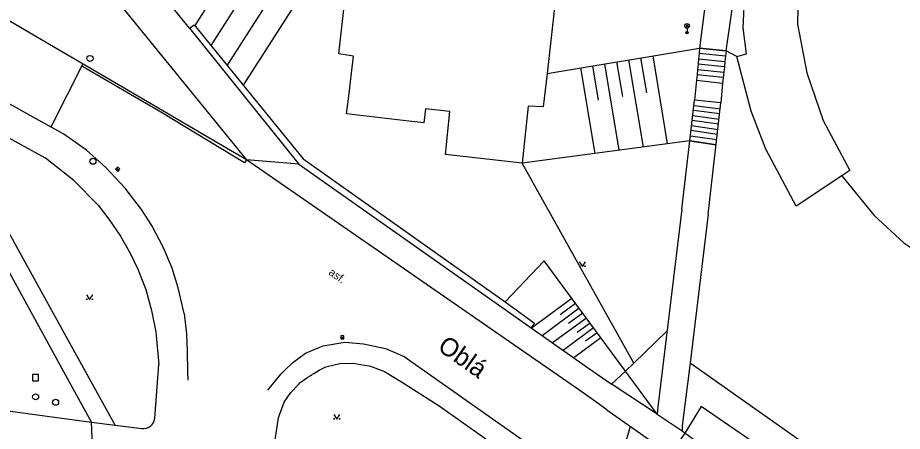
# Model space of a CAD drawing. Extents: x -602419 to -601554, y -1162937 to -1162362.
# Drawn here: x -602032.9 to -601960.3, y -1162522.5 to -1162488.6 of the extents above; entities that cross this region are included whole.
import ezdxf

# ---------------------------------------------------------------- set-up
doc = ezdxf.new("R2010")
doc.units = 0
doc.layers.add('Podklad', color=7, linetype='Continuous')

msp = doc.modelspace()

# ---------------------------------------------------------------- linework, layer by layer
at = {"layer": 'Podklad'}
for p, q in [((-601978.0925, -1162489.38), (-601977.8275, -1162489.115)), ((-601978.0925, -1162489.115), (-601977.8275, -1162489.38)), ((-601977.96, -1162489.435), (-601977.96, -1162489.81)), ((-602024.7616, -1162500.9249), (-602024.5784, -1162501.0951)), ((-602006.3692, -1162514.8113), (-602006.1192, -1162514.8113)), ((-602001.1665, -1162516.3917), (-601988.13, -1162525.56)), ((-601998.3077, -1162520.4323), (-601988.11, -1162527.62)), ((-602011.79, -1162523.58), (-602011.4808, -1162521.4155))]:
    msp.add_line(p, q, dxfattribs=at)
for points in [[(-602031.84, -1162478.48), (-602029.24, -1162481.61), (-602023.2199, -1162489.02), (-602016.15, -1162497.71), (-602014.38, -1162499.9), (-602014.09, -1162500.25)], [(-602014.09, -1162482.53), (-602018.35, -1162489.21)], [(-601974.75, -1162491.29), (-601973.52, -1162482.74)], [(-602012.4099, -1162483.61), (-602017.02, -1162490.85)], [(-601975.96, -1162483.38), (-601976.93, -1162491.06)], [(-602018.77, -1162489.42), (-602022.39, -1162484.96)], [(-602010.7199, -1162484.68), (-602015.69, -1162492.48)], [(-602009.03, -1162485.76), (-602014.36, -1162494.12)], [(-602030.92, -1162490.38), (-602037.98, -1162486.24)], [(-601965.26, -1162501.56), (-601969.02, -1162504.04), (-601971.5, -1162499.36), (-601972.71, -1162496.25), (-601973.89, -1162491.75), (-601973.08, -1162491.53), (-601973.36, -1162489.4099), (-601973.23, -1162486.48), (-601968.85, -1162486.43)], [(-601968.85, -1162486.43), (-601968.89, -1162489.1), (-601968.13, -1162493.1), (-601966.8, -1162497), (-601964.61, -1162501.12), (-601965.26, -1162501.56)], [(-602006.53, -1162491.55), (-602006.08, -1162487.64)], [(-601988.83, -1162487.74), (-601989.44, -1162493.14)], [(-602018.77, -1162489.42), (-602018.39, -1162489.1599), (-602015.19, -1162493.1), (-602013.4099, -1162495.29), (-602009.46, -1162500.15), (-601992.88, -1162511.9)], [(-602018.77, -1162489.42), (-602009.81, -1162500.58), (-601990.76, -1162514.04)], [(-602024.28, -1162494.27), (-602030.92, -1162490.38)], [(-602032.09, -1162496.4699), (-602041.27, -1162491.36)], [(-602005.31, -1162491.7199), (-602006.53, -1162491.55)], [(-601989.44, -1162493.14), (-601976.93, -1162491.06)], [(-601976.93, -1162491.06), (-601976.9699, -1162491.5), (-601977.02, -1162491.94), (-601977.06, -1162492.38), (-601977.1, -1162492.82), (-601977.14, -1162493.26), (-601977.19, -1162493.7), (-601977.34, -1162495.33)], [(-601974.8, -1162491.73), (-601976.9699, -1162491.5)], [(-601974.75, -1162491.29), (-601976.93, -1162491.06)], [(-601976.93, -1162491.06), (-601974.75, -1162491.29)], [(-601974.75, -1162491.29), (-601974.8, -1162491.73), (-601974.85, -1162492.17), (-601974.9, -1162492.61), (-601974.95, -1162493.05), (-601975, -1162493.49), (-601975.05, -1162493.94), (-601975.18, -1162495.57)], [(-601973.89, -1162491.75), (-601974.75, -1162491.29)], [(-602005.73, -1162495.2199), (-602005.31, -1162491.7199)], [(-601983.74, -1162492.19), (-601983.27, -1162495.04)], [(-601982.76, -1162492.03), (-601981.57, -1162499.19)], [(-601981.77, -1162491.86), (-601981.29, -1162494.74)], [(-601980.78, -1162491.7), (-601979.58, -1162498.92)], [(-601977.02, -1162491.94), (-601974.85, -1162492.17)], [(-602029.96, -1162497.1999), (-602027.61, -1162492.5399)], [(-602027.61, -1162492.5399), (-602027.5271, -1162492.3677)], [(-602009.81, -1162500.58), (-602014.09, -1162500.25), (-602014.2669, -1162500.497), (-602021.13, -1162496.3299), (-602027.61, -1162492.5399)], [(-601986.7, -1162492.68), (-601985.53, -1162499.7199)], [(-601985.7199, -1162492.52), (-601985.25, -1162495.35)], [(-601984.73, -1162492.36), (-601983.55, -1162499.45)], [(-601977.1, -1162492.82), (-601974.95, -1162493.05)], [(-601974.9, -1162492.61), (-601977.06, -1162492.38)], [(-601989.44, -1162493.14), (-601989.76, -1162495.9)], [(-601977.19, -1162493.7), (-601975.05, -1162493.94)], [(-601977.19, -1162493.7), (-601975.05, -1162493.94)], [(-601975, -1162493.49), (-601977.14, -1162493.26)], [(-602016.4, -1162498.89), (-602024.28, -1162494.27)], [(-602032.58, -1162499), (-602039.73, -1162495.07), (-602033.87, -1162505.71)], [(-602005.89, -1162496.4699), (-602005.73, -1162495.2199)], [(-601990.99, -1162495.83), (-601991.5, -1162500.52)], [(-601989.76, -1162495.9), (-601990.99, -1162495.83)], [(-601977.74, -1162498.67), (-601977.34, -1162495.33)], [(-601977.39, -1162495.79), (-601975.23, -1162496.05)], [(-601975.18, -1162495.57), (-601977.34, -1162495.33)], [(-601975.18, -1162495.57), (-601977.34, -1162495.33)], [(-601976.23, -1162504.71), (-601975.18, -1162495.57)], [(-602025.64, -1162500.88), (-602027.23, -1162499.44), (-602029.08, -1162498.14), (-602032.09, -1162496.4699)], [(-602000.79, -1162497.06), (-602005.89, -1162496.4699)], [(-601999.4099, -1162496.04), (-601999.56, -1162497.21)], [(-601997.42, -1162496.27), (-601999.4099, -1162496.04)], [(-601997.78, -1162499.8), (-601997.42, -1162496.27)], [(-601977.48, -1162496.61), (-601975.33, -1162496.89)], [(-601975.28, -1162496.4699), (-601977.44, -1162496.2)], [(-602030.1432, -1162497.5501), (-602030.1151, -1162497.4968), (-602030.0159, -1162497.3067), (-602029.96, -1162497.1999)], [(-601999.56, -1162497.21), (-602000.79, -1162497.06)], [(-601975.38, -1162497.32), (-601977.53, -1162497.02)], [(-601975.48, -1162498.1599), (-601977.64, -1162497.84)], [(-601977.59, -1162497.43), (-601975.42, -1162497.74)], [(-601977.74, -1162498.67), (-601991.5, -1162500.52)], [(-601978.4, -1162504.28), (-601977.74, -1162498.67)], [(-601977.74, -1162498.67), (-601975.575, -1162499.0083)], [(-601975.57, -1162499.01), (-601977.7199, -1162498.67)], [(-601977.69, -1162498.26), (-601975.53, -1162498.58)], [(-602026.27, -1162503.96), (-602028.26, -1162501.93), (-602030.58, -1162500.1), (-602032.58, -1162499)], [(-602014.09, -1162500.25), (-602016.4, -1162498.89)], [(-601986.76, -1162519.18), (-602014.09, -1162500.25)], [(-601991.5, -1162500.52), (-601997.78, -1162499.8)], [(-602019.7, -1162510.73), (-602020.2, -1162509.12), (-602020.9099, -1162507.46), (-602021.86, -1162505.64), (-602022.7, -1162504.31), (-602024.05, -1162502.55), (-602025.64, -1162500.88)], [(-601982.334, -1162516.9369), (-601991.5, -1162500.52)], [(-601965.26, -1162501.56), (-601962.6, -1162504.8), (-601960.17, -1162507.05), (-601956.1599, -1162509.73), (-601952.46, -1162511.99), (-601952.9699, -1162512.85), (-601945.68, -1162517.34), (-601944.8, -1162515.73)], [(-602026.27, -1162503.96), (-602025.38, -1162505.1), (-602024.43, -1162506.49), (-602023.61, -1162507.96), (-602023.01, -1162509.21), (-602022.37, -1162510.88), (-602021.89, -1162512.6), (-602021.54, -1162514.35), (-602021.39, -1162515.85), (-602021.3, -1162517.03)], [(-601978.4, -1162504.28), (-601980.35, -1162520.52)], [(-601976.23, -1162504.71), (-601977.7199, -1162516.9)], [(-602028.59, -1162515.28), (-602033.87, -1162505.71)], [(-602029.08, -1162517.65), (-602034.33, -1162508.09)], [(-601980.42, -1162521.1), (-601989.67, -1162508.54), (-601992.88, -1162511.9)], [(-601986.8, -1162508.615), (-601986.55, -1162508.99), (-601986.3, -1162508.615)], [(-602019.2199, -1162512.84), (-602019.7, -1162510.73)], [(-602027.2182, -1162511.3309), (-602026.9682, -1162511.7059), (-602026.7182, -1162511.3309)], [(-601992.88, -1162511.9), (-601990.4699, -1162513.64), (-601990.76, -1162514.04)], [(-601987.4, -1162511.62), (-601990.73, -1162514.06)], [(-601986.81, -1162512.42), (-601989.86, -1162514.67)], [(-601987.11, -1162512.02), (-601988.38, -1162512.96)], [(-602019.2199, -1162512.84), (-602019.03, -1162514.52), (-602018.96, -1162515.96), (-602018.95, -1162517.58), (-602018.92, -1162518.31)], [(-601986.2199, -1162513.23), (-601989, -1162515.27)], [(-601986.52, -1162512.83), (-601987.68, -1162513.68)], [(-601990.76, -1162514.04), (-601986.32, -1162517.14)], [(-601985.63, -1162514.03), (-601988.13, -1162515.88)], [(-601985.92, -1162513.63), (-601986.98, -1162514.4099)], [(-601985.33, -1162514.44), (-601986.28, -1162515.13)], [(-601982.334, -1162516.9369), (-601979.6, -1162514.274)], [(-602024.88, -1162522.02), (-602028.59, -1162515.28)], [(-602012.35, -1162519.13), (-602011.247, -1162517.7989), (-602010.916, -1162517.4771), (-602010.3042, -1162516.8829), (-602009.2577, -1162516.0929), (-602008.2241, -1162515.6738), (-602007.8079, -1162515.505), (-602006.032, -1162515.2119), (-602005.7069, -1162515.2371), (-602004.4929, -1162515.3318), (-602002.698, -1162515.719), (-602001.1665, -1162516.3917)], [(-601985.03, -1162514.84), (-601987.26, -1162516.48)], [(-602011.4808, -1162521.4155), (-602011.3907, -1162521.1769), (-602010.997, -1162520.1369), (-602010.4702, -1162519.3229), (-602009.8337, -1162518.6677), (-602009.693, -1162518.5229), (-602009.3341, -1162518.2689), (-602009.0702, -1162518.0838), (-602008.8908, -1162517.9632), (-602008.7788, -1162517.8918), (-602008.5821, -1162517.772), (-602008.3578, -1162517.6401), (-602008.1297, -1162517.5122), (-602007.927, -1162517.403), (-602007.583, -1162517.2222), (-602006.9092, -1162517.0639), (-602006.4528, -1162516.9588), (-602005.359, -1162516.9359), (-602004.744, -1162517.031), (-602004.0368, -1162517.1429), (-602003.9191, -1162517.1859), (-602002.7712, -1162517.6122), (-602001.3957, -1162518.4511), (-601998.3077, -1162520.4323)], [(-601984.1628, -1162518.6431), (-601983.0169, -1162517.5739), (-601982.334, -1162516.9369)], [(-601977.7199, -1162516.9), (-601978.35, -1162522.08)], [(-601977.7199, -1162516.9), (-601956.9099, -1162531.58), (-601954.44, -1162533.26), (-601952.87, -1162534.1599)], [(-602026.82, -1162521.76), (-602029.08, -1162517.65)], [(-602021.63, -1162521.44), (-602021.3, -1162517.03)], [(-601986.32, -1162517.14), (-601984.9699, -1162518.08)], [(-601984.9699, -1162518.08), (-601984.11, -1162518.68)], [(-601980.42, -1162521.1), (-601984.11, -1162518.68)], [(-601985.64, -1162519.9699), (-601986.76, -1162519.18)], [(-602036.7, -1162520.44), (-602029.84, -1162521.36)], [(-601984.54, -1162520.75), (-601985.64, -1162519.9699)], [(-601980.35, -1162520.52), (-601980.42, -1162521.1)], [(-601934.5953, -1162546.3375), (-601934.4053, -1162544.2963), (-601934.395, -1162544.1839), (-601934.035, -1162541.6329), (-601941.491, -1162540.521), (-601946.887, -1162539.0499), (-601952.218, -1162537.284), (-601953.5449, -1162536.4029), (-601953.8289, -1162536.2141), (-601956.502, -1162534.4389), (-601976.81, -1162520.475), (-601978.14, -1162522.6591), (-601979.356, -1162524.4)], [(-602006.94, -1162521.145), (-602006.69, -1162521.52), (-602006.44, -1162521.145)], [(-601984.54, -1162520.75), (-601979.57, -1162524.25), (-601975.29, -1162527.25)], [(-601980.42, -1162521.1), (-601978.37, -1162522.49)], [(-602029.84, -1162521.36), (-602026.82, -1162521.76)], [(-602024.79, -1162525.27), (-602026.68, -1162525.03), (-602026.82, -1162521.76), (-602024.88, -1162522.02)], [(-602024.88, -1162522.02), (-602022.69, -1162522.29)], [(-602022.69, -1162522.29), (-602022.51, -1162522.3), (-602022.31, -1162522.26), (-602022.12, -1162522.19), (-602021.98, -1162522.09), (-602021.84, -1162521.95), (-602021.74, -1162521.8), (-602021.67, -1162521.63), (-602021.63, -1162521.44)], [(-601987.89, -1162527.76), (-601984.4098, -1162528.1838), (-601984.36, -1162528.1899), (-601982.6096, -1162522.1094)], [(-601978.35, -1162522.08), (-601978.37, -1162522.49), (-601974.85, -1162525.08)]]:
    msp.add_lwpolyline(points, dxfattribs=at)
for points in [[(-602024.8467, -1162501.0165), (-602024.6635, -1162501.1867), (-602024.4933, -1162501.0035), (-602024.6765, -1162500.8333)], [(-602006.3692, -1162514.9363), (-602006.1192, -1162514.9363), (-602006.1192, -1162514.6863), (-602006.3692, -1162514.6863)], [(-602031.6599, -1162518.37), (-602031.1599, -1162518.37), (-602031.1599, -1162517.87), (-602031.6599, -1162517.87)]]:
    msp.add_lwpolyline(points, close=True, dxfattribs=at)
for centre, radius in [((-601977.96, -1162489.2475), 0.1875), ((-601977.96, -1162489.81), 0.1), ((-601977.96, -1162489.81), 0.0723), ((-601977.96, -1162489.81), 0.0438), ((-602026.94, -1162491.92), 0.25), ((-602026.7, -1162500.35), 0.25), ((-601986.7751, -1162508.9649), 0.025), ((-601986.3254, -1162508.9649), 0.025), ((-602027.1933, -1162511.6808), 0.025), ((-602026.7436, -1162511.6808), 0.025), ((-602031.4, -1162519.69), 0.25), ((-602029.76, -1162520.13), 0.25), ((-602006.9151, -1162521.4949), 0.025), ((-602006.4654, -1162521.4949), 0.025)]:
    msp.add_circle(centre, radius, dxfattribs=at)

# ---------------------------------------------------------------- texts
for s, height, rotation, p in [('asf.', 0.65, 325.72, (-602007.4192, -1162509.6152)), ('Oblá', 1.5, 324.8, (-601998.5163, -1162515.7894))]:
    msp.add_text(s, height=height, rotation=rotation, dxfattribs=at).set_placement(p)

doc.saveas('drawing.dxf')
